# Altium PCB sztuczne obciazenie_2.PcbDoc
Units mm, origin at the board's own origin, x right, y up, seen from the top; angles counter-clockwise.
Board outline 83 x 78.5 mm, 2 copper layers (Top Layer, Bottom Layer); 51 components, 49 nets, 181 pads, 10 vias.
Unrouted connection lines stored in the file: 2.
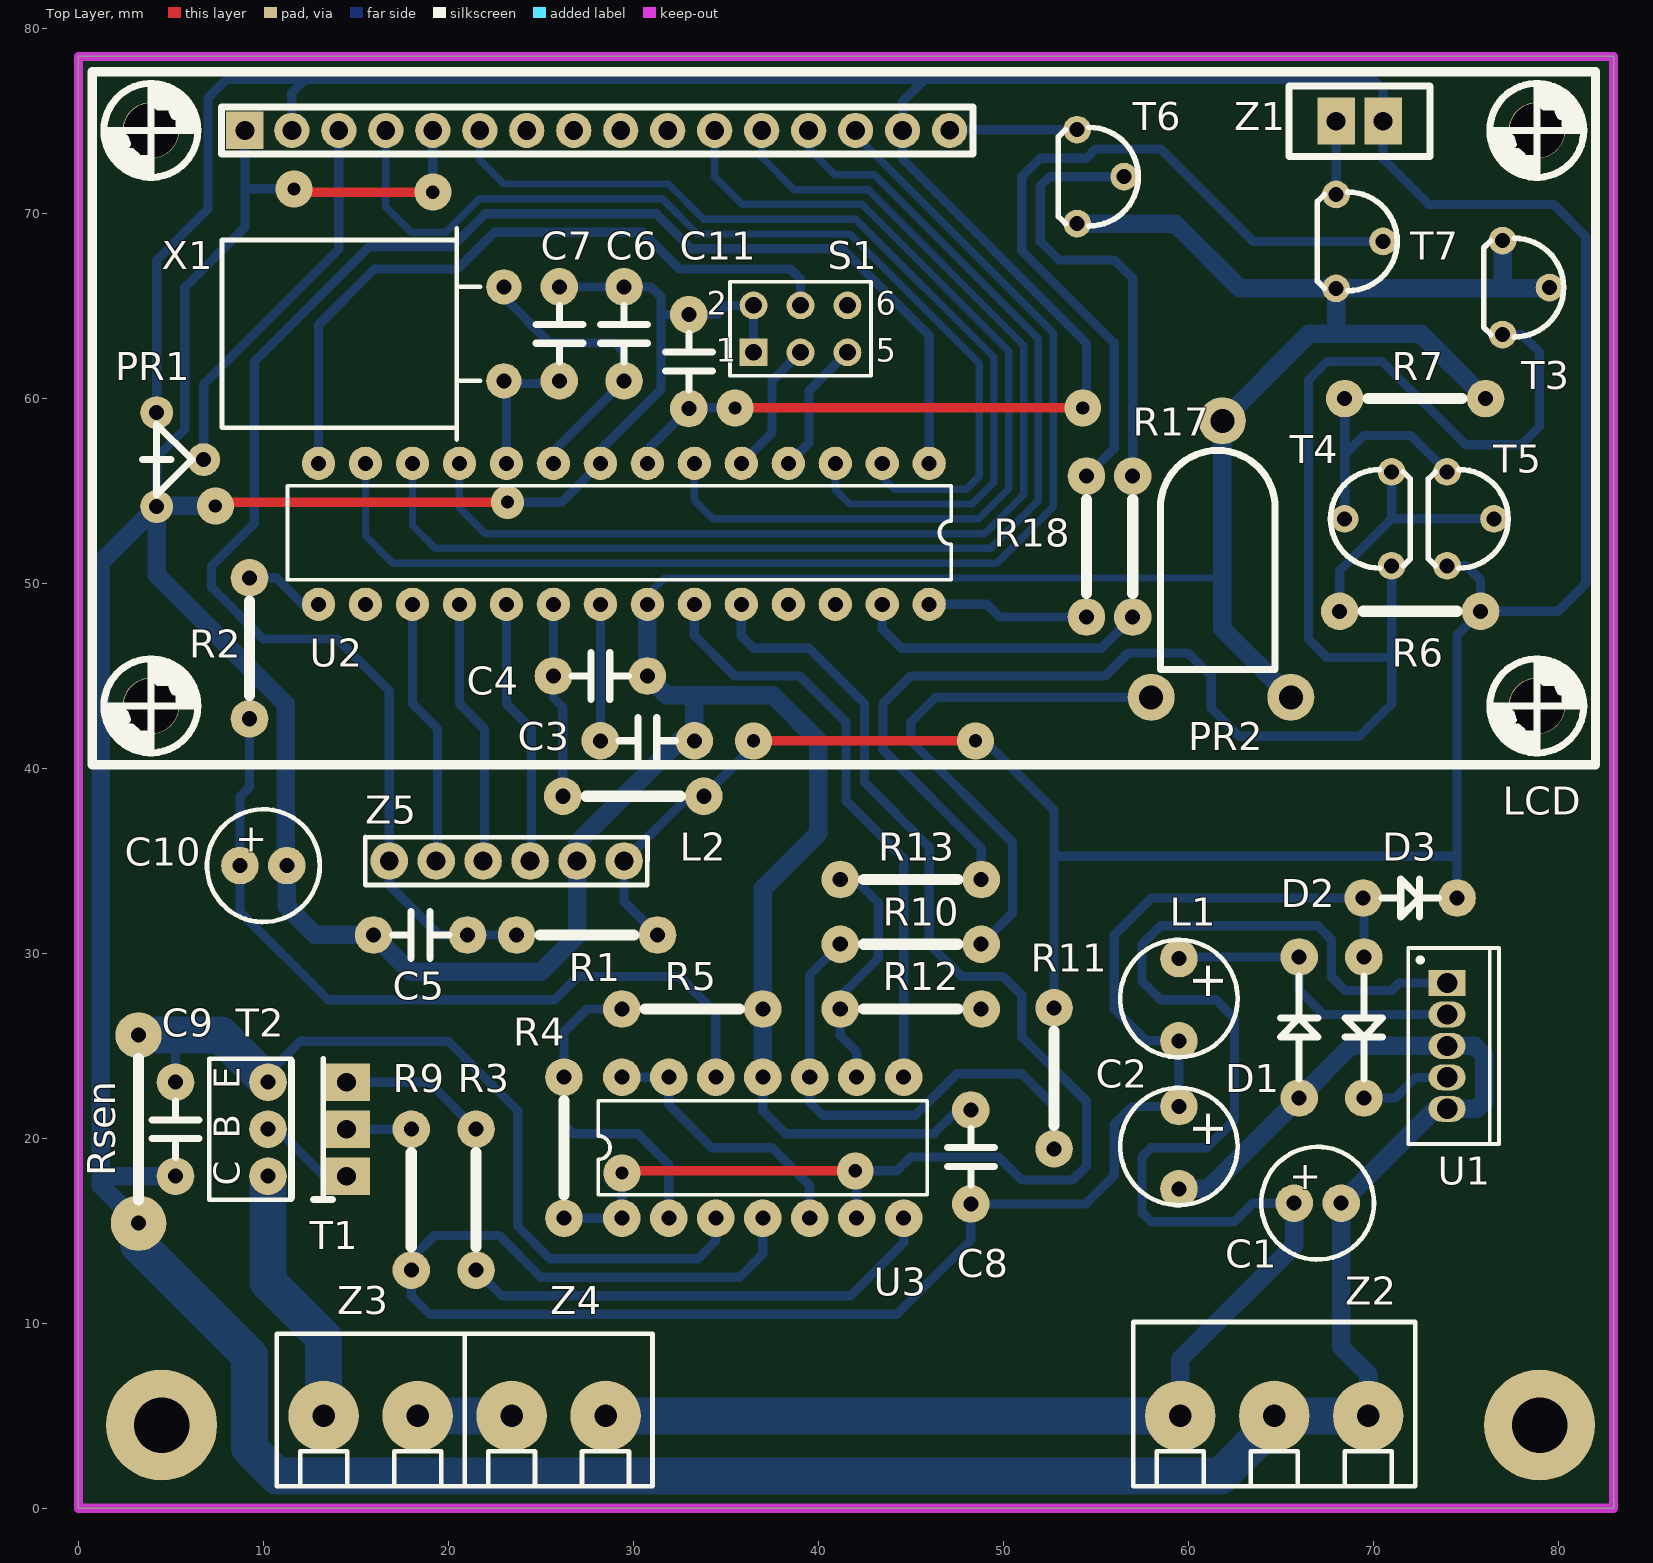
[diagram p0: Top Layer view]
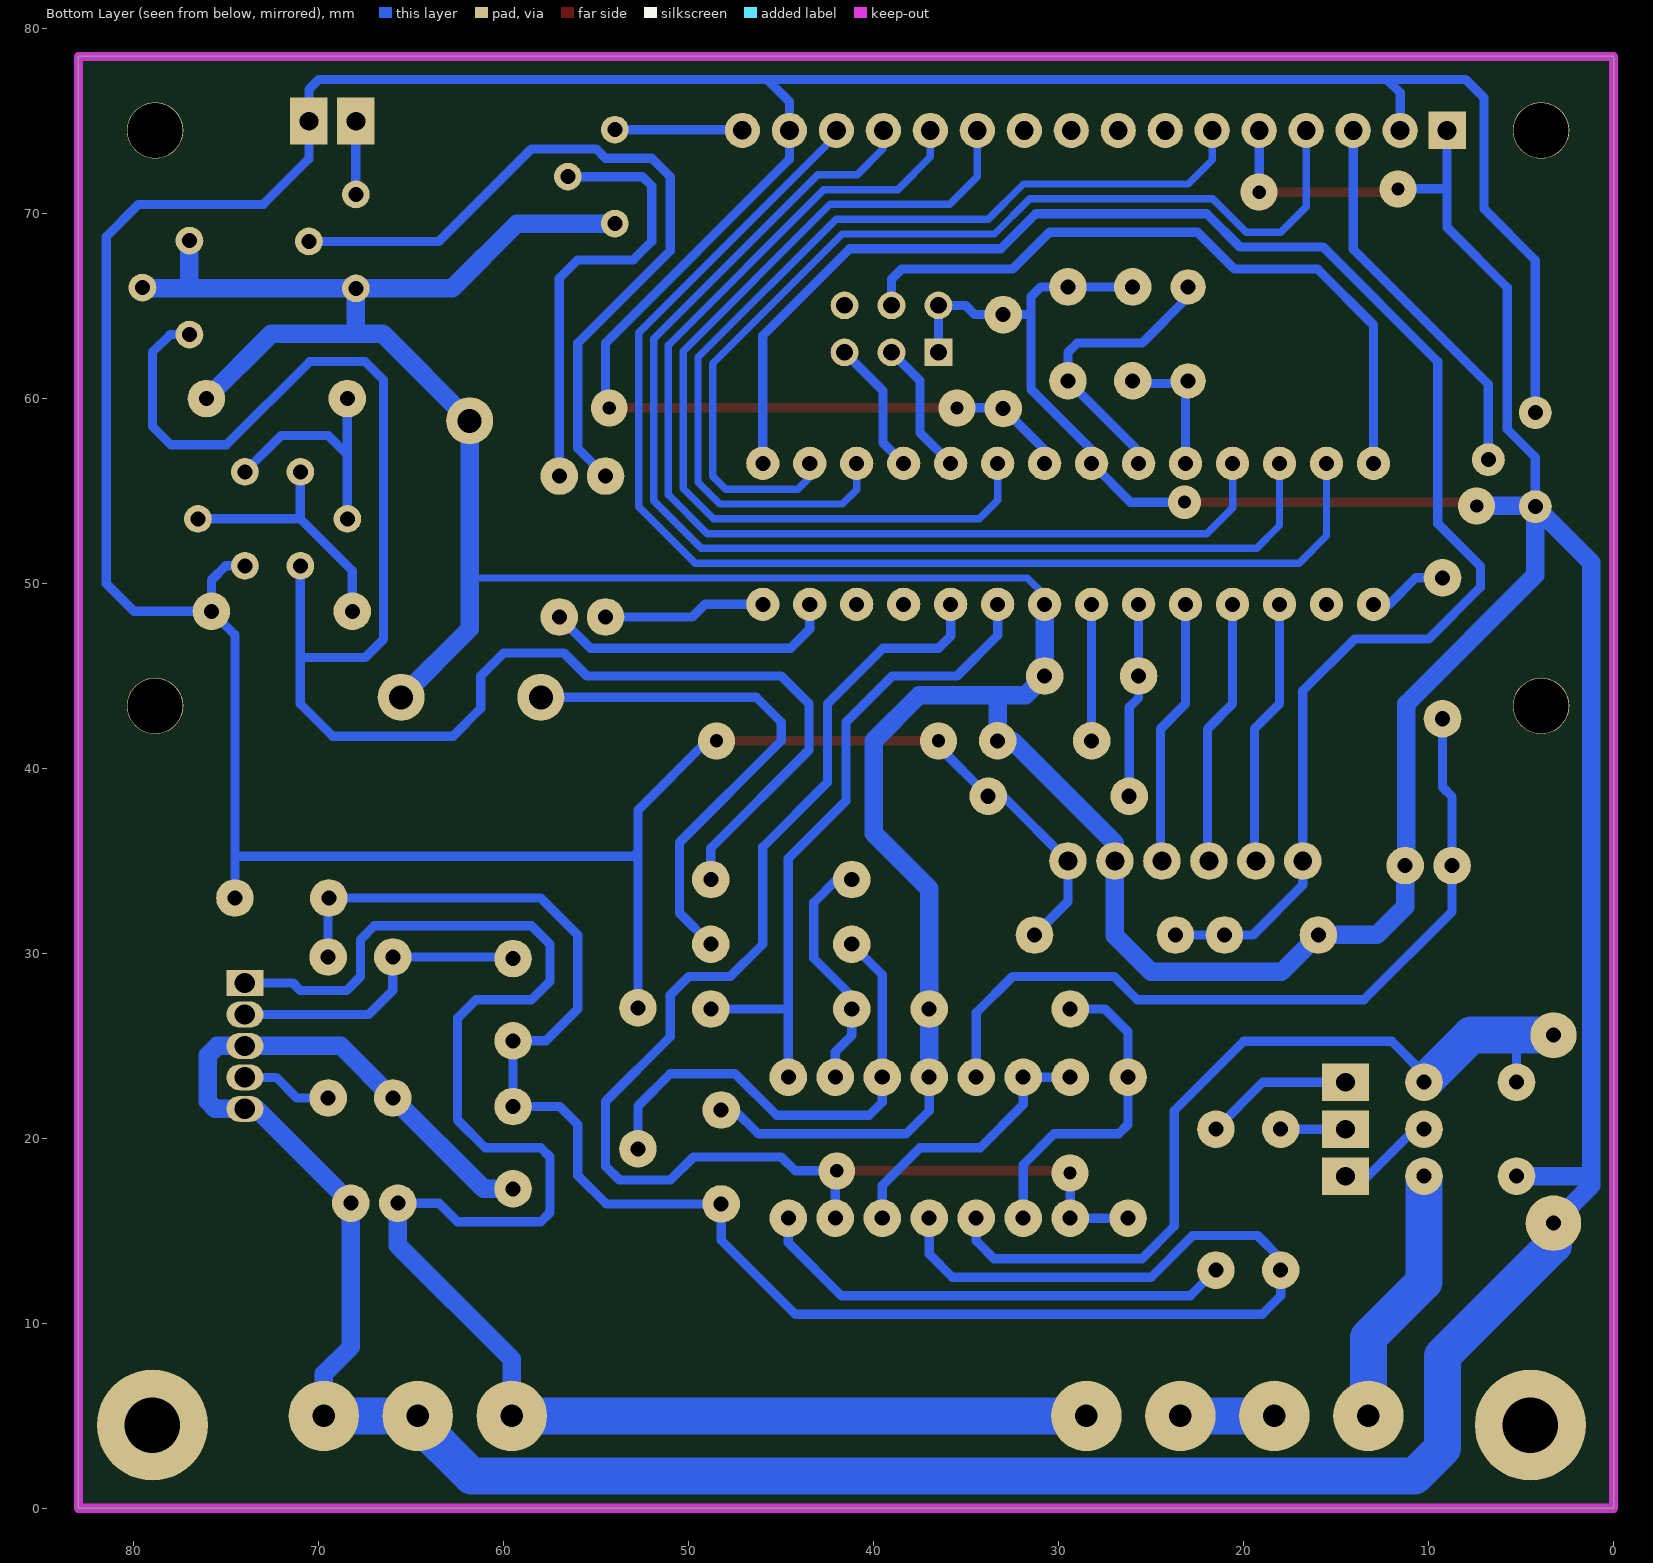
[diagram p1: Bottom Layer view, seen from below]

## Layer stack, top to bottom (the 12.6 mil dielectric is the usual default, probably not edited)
Top Layer: signal copper 0.0356
Dielectric: dielectric 0.32, FR-4, Dk 4.8
Bottom Layer: signal copper 0.0356

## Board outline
0,0 83,0 83,78.5 0,78.5

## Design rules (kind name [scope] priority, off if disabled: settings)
Clearance [All] p1: gap=0.3
PolygonConnect [All] p1: connectstyle=Relief reliefconductorwidth=0.254 reliefentries=4 polygonreliefangle="90 Angle"
RoutingVias [All] p1: holewidth=0.8 width=2 viastyle="Through Hole" minholewidth=0.711 minwidth=2 maxholewidth=1 maxwidth=2
SilkscreenOverComponentPads [All] p1: minsilkscreentomaskgap=0.254
SolderMaskExpansion [All] p1: expansion=0.102
Width [All] p1: maxlimit=3 minlimit=0.3 preferedwidth=0.5 minimp=50.000000 maximp=50.000000 favimp=50.000000
27 further rules are at their usual default settings.

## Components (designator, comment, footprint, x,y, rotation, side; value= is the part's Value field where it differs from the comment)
C1 "100uF" CE6 67,16.5 r0 top
C2 "100uF" CE7 59.5,19.5 r270 top
C3 "100n" C2 30.76,41.5 r0 top
C4 "100n" C2 28.22,45 r0 top
C5 "100n" C2 18.5,31 r180 top
C6 "C" C2 29.5,63.5 r270 top
C7 "C" C2 26,63.5 r90 top
C8 "100n" C2 48.25,19 r270 top
C9 "100n" C2 5.25,20.5 r90 top
C10 "2,2uF" CE6 10,34.75 r0 top
C11 "100n" C2 33,62 r270 top
D1 "" D3 66,26 r90 top
D2 "HER105" D3 69.5,26 r270 top
D3 "HER105" D2 72,33 r0 top
L1 "330uH" CE7 59.5,27.5 r270 top
L2 "" R3 30,38.5 r90 top
LCD "LCD 2x16" LCD16*2_B 9,74.5 r0 top locked
PR1 "" PR 5.5,56.7 r270 top
PR2 "POT" PR7 60,40 r90 top
R1 "10k" R3 27.5,31 r270 top
R2 "47k" R3 9.25,46.5 r180 top
R3 "100R" R3 21.5,16.69 r0 top
R4 "100k" R3 26.25,19.5 r0 top
R5 "47k+2,2k" R3 33.19,27 r90 top
R6 "R" R3 72,48.5 r90 top
R7 "R" R3 72.27,60 r270 top
R9 "10R" R3 18,16.69 r180 top
R10 "" R3 45,30.5 r90 top
R11 "" R3 52.75,23.25 r0 top
R12 "" R3 45,27 r90 top
R13 "" R3 45,34 r270 top
R17 "10k" R3 57,52 r0 top
R18 "10k" R3 54.5,52 r180 top
Rsen "0.11R/18W" R4 3.25,20.5 r0 top
S1 "Enkoder" HDR2X3 36.5,62.5 r0 top
T1 "BD139" BD1 14.5,20.5 r90 top
T2 "ISOBUV21" TUNIW 10.25,20.5 r90 top
T3 "BC557B" T_1 77,66 r270 top
T4 "BC557B" T_1 71,53.5 r90 top
T5 "BC557B" T_1 74,53.5 r270 top
T6 "NPN" T_1 54,72 r270 top
T7 "NPN" T_1 68,68.5 r270 top
U1 "LM2575T-5.0" T05A 74,25 r270 top
U2 "ATmega8-16PC" U28_MALA 46,56.5 r180 top
U3 "" U14 37,19.5 r0 top
X1 "" X 23,63.5 r180 top
Z1 "FAN" JMP2 69.27,75 r90 top
Z2 "Vin" ARK3 64.653,5 r180 top
Z3 "LOAD" ARK2 18.34,5 r180 top
Z4 "Vext" ARK2 28.5,5 r180 top
Z5 "ISP" "GOLDPIN 6" 31.5,25.5 r180 top

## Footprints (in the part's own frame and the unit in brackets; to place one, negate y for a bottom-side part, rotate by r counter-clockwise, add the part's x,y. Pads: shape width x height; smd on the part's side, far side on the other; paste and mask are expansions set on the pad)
ARK2 [mil]
  round 150 hole 48: 1(200,0) 2(0,0)
  silkscreen extent -100,-175 300,150
ARK3 [mil]
  round 150 hole 48: 1(200,0) 2(0,0) 3(-200,0)
  silkscreen extent -300,-200 300,150
BD1 [mil]
  rect 80x100 hole 40: 1(-100,0) 2(100,0) 3(0,0)
  silkscreen extent -150,30 150,70
C2 [mil]
  round 80 hole 32: 1(-100,0) 2(100,0)
  silkscreen extent -60,-50 60,50
CE6 [mil]
  round 80 hole 32: 1(-50,0) 2(50,0)
  silkscreen extent -120,-120 120,120
CE7 [mil]
  round 80 hole 32: 1(-87.5,0) 2(87.5,0)
  silkscreen extent -127,-125 122,125
D2 [mil]
  round 80 hole 32: 1(-100,0) 2(100,0)
  silkscreen extent -60,-40 60,40
D3 [mil]
  round 80 hole 32: 1(-150,0) 2(150,0)
  silkscreen extent -110,-40 110,40
"GOLDPIN 6" [mil]
  round 80 hole 40: 1(78.74,-374.02) 2(178.74,-374.02) 3(278.74,-374.02) 4(378.74,-374.02) 5(478.74,-374.02) 6(578.74,-374.02)
  silkscreen extent 29,-425 630,-323
HDR2X3 [mm] "Connector; Header; 3x2 Position"
  rect 1.5x1.5 hole 0.9: 1(0,0)
  round 1.5 hole 0.9: 2(0,2.54) 3(2.54,0) 4(2.54,2.54) 5(5.08,0) 6(5.08,2.54)
  silkscreen extent -1.27,-1.27 6.35,3.81
JMP2 [mil]
  rect 100x80 hole 40: 1(0,-50) 2(0,50)
  silkscreen extent -75,-150 75,150
LCD16*2_B [mil]
  round 120 hole 117: 0(-200,-1225) 0(-200,0) 0(2750,-1225) 0(2750,0)
  rect 80x80 hole 40: 1(0,0)
  round 75 hole 40: 2(100,0) 3(200,0) 4(300,0) 5(400,0) 6(500,0) 7(600,0) 8(700,0) 9(800,0) 10(900,0) 11(1000,0) 12(1100,0) 13(1200,0) 14(1300,0) 15(1400,0)
  round 75 hole 39.37: 16(1500,0)
  silkscreen extent -325,-1350 2875,125
PR [mil]
  round 70 hole 32: 1(100,-50) 2(0,50) 3(-100,-50)
  silkscreen extent -75,-80 75,25
PR7 [mm]
  round 2.54 hole 1.295: 1(3.85,2) 2(18.8,-1.85) 3(3.85,-5.55)
  silkscreen extent 5.35,-4.7 17.2,1.5
R3 [mil]
  round 80 hole 32: 1(0,-150) 2(0,150)
  silkscreen extent 0,-100 0,100
R4 [mm]
  round 3 hole 0.813: 1(0,-5.08)
  round 2.5 hole 0.813: 2(0,5.08)
  silkscreen extent 0,-3.81 0,3.81
T05A [mm] "TO, Thru-Hole, Vertical, Heatsink Mounted; 5 In-Line Leads; Pitch 1.70 mm"
  rect 1.4x2 hole 1.1: 1(-3.4,0)
  oval 1.4x2 hole 1.1: 2(-1.7,0) 3(0,0) 4(1.7,0) 5(3.4,0)
  silkscreen extent -5.3,-2.1 5.3,2.8, body extent -5.35,-2.15 5.35,2.85, height 19.6
T_1 [mm]
  round 1.5 hole 0.813: 1(2.54,0) 2(0,2.54) 3(-2.54,0)
  silkscreen extent -2.67,-1.02 2.67,3.3
TUNIW [mil]
  round 80 hole 32: 1(100,0) 2(0,0) 3(-100,0)
  silkscreen extent -150,-50 150,125
U14 [mil]
  round 80 hole 32: 1(-300,-150) 2(-200,-150) 3(-100,-150) 4(0,-150) 5(100,-150) 6(200,-150) 7(300,-150) 8(300,150) 9(200,150) 10(100,150) 11(0,150) 12(-100,150) 13(-200,150) 14(-300,150)
  silkscreen extent -350,-100 350,100
U28_MALA [mm]
  round 1.8 hole 0.813: 1(0,0) 2(2.54,0) 3(5.08,0) 4(7.62,0) 5(10.16,0) 6(12.7,0) 7(15.24,0) 8(17.78,0) 9(20.32,0) 10(22.86,0) 11(25.4,0) 12(27.94,0) 13(30.48,0) 14(33.02,0) 15(33.02,7.62) 16(30.48,7.62) 17(27.94,7.62) 18(25.4,7.62) 19(22.86,7.62) 20(20.32,7.62) 21(17.78,7.62) 22(15.24,7.62) 23(12.7,7.62) 24(10.16,7.62) 25(7.62,7.62) 26(5.08,7.62) 27(2.54,7.62) 28(0,7.62)
  silkscreen extent -1.19,1.21 34.7,6.3
X [mil]
  round 75 hole 32: 1(0,100) 2(0,-100)
  silkscreen extent 50,-225 600,225

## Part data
C1 C2 C10: library part EL, "Elektrolit"
C3 C4 C5 C8 C9 C11: library part C, "Kondensator"
C6 C7: "Kondensator"
D1: library part "D SCHOTTKY", "Dioda Schottky"
D2 D3: library part D, "Dioda"
L1 L2: library part L2, "Cewka"
LCD: library part LCD
PR1: library part POT, "Potencjometr"
PR2: "Potencjometr"
R1 R2 R3 R4 R5 R9 R10 R11 R12 R13 R17 R18 Rsen: library part R, "Rezystor"
R6 R7: "Rezystor"
T1 T2: library part NPN, "Tranzystor NPN"
T3 T4 T5: library part PNP, "Tranzystor PNP"
T6 T7: "Tranzystor NPN"
U1: "SIMPLE SWITCHER® 1A Step-Down Voltage Regulator, 5-pin TO-220"
U2: "8-Bit AVR Microcontroller with 8K Bytes of In-System Programmable Flash Memory"
U3: library part LM324
X1: library part X
Z1: library part JMP2
Z2: library part "ARK 3"
Z3 Z4: library part ARK2
Z5: library part GOLDPINX6

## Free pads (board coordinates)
  round 6 hole 3: 0(79,4.5) 1(4.5,4.5)

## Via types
v1: diameter 2, hole 0.711, Top Layer to Bottom Layer, 9 vias
v2: diameter 1.8, hole 0.711, Top Layer to Bottom Layer, 1 vias

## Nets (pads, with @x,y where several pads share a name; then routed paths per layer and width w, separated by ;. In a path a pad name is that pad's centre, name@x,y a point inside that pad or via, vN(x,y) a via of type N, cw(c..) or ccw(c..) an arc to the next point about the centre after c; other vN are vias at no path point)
+6V: C2.1 C8.2 D2.1 D3.1 L1.2 R9.2 U3.4 | length 103.5
  Bottom Layer w0.5: U3.4 37,13.75 35.75,12.5 25,12.5 22.75,14.75 19.25,14.75 18,13.5 R9.2 18,11.5 19,10.5 44.25,10.5 48.25,14.5 C8.2 54.46,16.46 56,18 56,20.75 56.972,21.722 C2.1 L1.2 57.722,25.278 56,27 56,31 58,33 D3.1 69.5,32.96 D2.1
GND: C1.2 C2.2 C3.2 C4.2 C5.2 C6.1 C7.2 C8.1 C9.1 C10.2 C11.1 D1.1 LCD.1 LCD.5 PR1.1 PR2.2 PR2.3 R5.1 R7.2 Rsen.1 S1.1 S1.2 T3.2 T3.3 T6.1 T7.1 U1.3 U1.5 U2.8 U2.22 U3.11 Z2.2 Z2.3 Z5.2 | length 457.5
  Top Layer w0.5: v1(7.4,54.2) 7.4,54.4 v2(23.2,54.4) ; v1(11.66,71.34) 11.66,71.16 v1(19.16,71.16)
  Bottom Layer w0.4: U2.22@30.76,49.36 31.7,50.3 61.85,50.3
  Bottom Layer w0.5: PR1.1@4.27,54.2 PR1.1 4.23,56.83 5.75,58.35 5.75,66 9,69.25 9,71.5 ; LCD.1 9,71.5 ; v1(11.66,71.34) 9.16,71.34 9,71.5 ; v1(19.16,71.16) LCD.5 ; v2(23.2,54.4) 26.12,54.4 U2.8 28.22,57.22 31.5,60.5 31.5,64.5 ; C7.2@25.46,66.04 C7.2 C6.1 30.96,66.04 31.5,65.5 31.5,64.5 ; U2.22 U2.22@30.76,49.36 ; S1.1 S1.2 35.04,65.04 34.54,64.54 C11.1 31.54,64.54 31.5,64.5 ; 36.81,33.31 37,33.5 ; U3.11 37,21.5 38.25,20.25 46.25,20.25 47.54,21.54 C8.1
  Bottom Layer w1: Rsen.1 1.2,17.47 1.2,18 ; PR1.1@4.27,54.2 v1(7.4,54.2) ; C9.1 1.24,17.96 1.2,18 ; U2.22 C4.2 31.81,43.95 33,43.95 ; U3.11 R5.1 37,33.5 40,36.5 40,41.5 37.55,43.95 33,43.95 ; T6.1 59.29,69.46 62.79,65.96 T7.1 ; C2.2 61.087,17.277 D1.1 68.81,25 U1.3 75.5,25 76,24.5 76,22 75.6,21.6 U1.5 73.37,21.6 C1.2 68.27,8.73 69.733,7.267 Z2.3 ; PR2.3 61.85,47.55 61.85,50.3 PR2.2 66.55,63.5 68,63.5 ; T7.1@68.04,66 T7.1 ; R7.2 72.58,63.5 68,63.5 ; T3.3 77,65.96 ; T3.2 79.5,65.96 77,65.96 ; 1.2,18 1.2,51.13 PR1.1 4.245,54.145 4.245,50.445 11.2,43.49 11.2,34.82 C10.2 11.27,32.53 12.8,31 C5.2 17.96,29 25,29 26.96,30.96 Z5.2 26.96,35.96 32.5,41.5 C3.2 33.3,43.65 33,43.95 ; 68,63.5 T7.1 ; T7.1 77,65.96
  Bottom Layer w2: Rsen.1 3.25,14.25 9.25,8.25 9.25,3.25 10.75,1.75 61.75,1.75 64.653,4.653 Z2.2 Z2.3
NetC3_1: C3.1 U2.21 | length 7.4
  Bottom Layer w0.5: C3.1 U2.21
NetC4_1: C4.1 L2.2 U2.20 | length 10.6
  Bottom Layer w0.5: U2.20 C4.1 25.68,43.82 26.19,43.31 L2.2
NetC5_1: C5.1 R1.1 U2.1 Z5.6 | length 93
  Bottom Layer w0.5: R1.1 C5.1 19.5,31 16.8,33.7 Z5.6 16.8,44.2 14,47 10,47 7.2,49.8 7.2,50.95 9.5,53.25 9.5,62 15.7,68.2 20.2,68.2 22,70 31.237,70 33.137,68.1 41.3,68.1 46,63.4 U2.1
NetC6_2: C6.2 U2.9 X1.2 | length 15.9
  Bottom Layer w0.5: X1.2 23,65.5 25.5,63 29,63 29.5,62.5 C6.2 25.68,57.14 U2.9
NetC7_1: C7.1 U2.10 X1.1 | length 7
  Bottom Layer w0.5: U2.10 23.14,60.82 C7.1@25.86,60.82
NetC9_2: C9.2 Rsen.2 T2.1 U3.3 | length 46.1
  Bottom Layer w0.5: C9.2 5.25,25.58 ; T2.1 10.25,23.5 12,25.25 20,25.25 23.75,21.5 23.75,15.25 25.5,13.5 33.5,13.5 34.46,14.46 U3.3
  Bottom Layer w2: Rsen.2 5.25,25.58 7.71,25.58 T2.1
NetC10_1: C10.1 R2.2 U3.12 | length 43.2
  Bottom Layer w0.5: R2.2 9.25,39 8.73,38.48 C10.1 8.73,32.27 13.5,27.5 25.75,27.5 27,28.75 32.5,28.75 34.46,26.79 U3.12
NetD1_2: D1.2 L1.1 U1.2 | length 16.9
  Bottom Layer w0.5: L1.1 59.587,29.81 D1.2 66,28 67.3,26.7 U1.2
NetD2_2: D2.2 U1.4 | length 5
  Bottom Layer w0.5: D2.2 71.19,22.19 72.3,23.3 U1.4
NetLCD_3: LCD.3 PR1.2 | length 20.4
  Bottom Layer w0.5: PR1.2@6.77,57.1 6.77,60.77 14.08,68.08 LCD.3
NetLCD_4: LCD.4 U2.2 | length 53.9
  Bottom Layer w0.4: LCD.4 16.62,70.38 18,69 19.869,69 21.669,70.8 31.569,70.8 33.469,68.9 41.7,68.9 48.7,61.9 48.7,55.8 48,55.1 44.1,55.1 43.46,55.74 U2.2
NetLCD_6: LCD.6 U2.3 | length 51.4
  Bottom Layer w0.4: LCD.6 21.7,72.9 23,71.6 31.9,71.6 33.8,69.7 42.031,69.7 49.5,62.231 49.5,55.469 48.331,54.3 41.7,54.3 40.92,55.08 U2.3
NetLCD_11: LCD.11 U2.6 | length 49.8
  Bottom Layer w0.4: U2.6 33.3,54.5 34.3,53.5 48.663,53.5 50.3,55.137 50.3,62.563 42.363,70.5 35.9,70.5 34.4,72 LCD.11
NetLCD_12: LCD.12 U2.11 | length 62.3
  Bottom Layer w0.4: U2.11 20.6,54.1 22,52.7 48.994,52.7 51.1,54.806 51.1,62.894 42.694,71.3 38.7,71.3 36.94,73.06 LCD.12
NetLCD_13: LCD.13 U2.12 | length 65.2
  Bottom Layer w0.4: U2.12 18.06,53.14 19.3,51.9 49.325,51.9 51.9,54.475 51.9,63.225 43.025,72.1 40.9,72.1 39.48,73.52 LCD.13
NetLCD_14: LCD.14 U2.13 | length 67.8
  Bottom Layer w0.4: U2.13 15.52,52.58 17,51.1 49.657,51.1 52.7,54.143 52.7,63.557 42.02,74.237 LCD.14
NetLCD_16: LCD.16 T6.3 | length 6.9
  Bottom Layer w0.5: LCD.16 47.14,74.54 T6.3
NetPR2_1: PR2.1 R10.1 | length 28.5
  Bottom Layer w0.5: R10.1 50.5,32.19 50.5,36 45,41.5 45,42.5 46.35,43.85 PR2.1
NetR2_1: R2.1 U2.15 | length 4.3
  Bottom Layer w0.5: R2.1 10.69,50.31 12.12,48.88 U2.15
NetR3_1: R3.1 U3.7 | length 26.2
  Bottom Layer w0.5: R3.1 22.88,11.5 41.75,11.5 44.62,14.37 U3.7
NetR3_2: R3.2 T1.2 | length 8.1
  Bottom Layer w0.5: T1.2 18.96,23.04 R3.2
NetR4_1: R4.1 U2.24 U3.1 U3.6 | length 75.7
  Top Layer w0.5: v1(29.38,18.13) 29.5,18.25 v1(42,18.25)
  Bottom Layer w0.5: R4.1 U3.1 v1(29.38,18.13) ; U2.24 35.84,47.16 36.5,46.5 39.5,46.5 42.5,43.5 42.5,39.25 46,35.75 46,30.5 47.75,28.75 50,28.75 51,27.75 51,25.5 54.5,22 54.5,18.5 53.75,17.75 51,17.75 49.75,19 45,19 44.25,18.25 v1(42,18.25) 42.08,18.17 U3.6
NetR4_2: R4.2 R5.2 U3.2 | length 18.1
  Bottom Layer w0.5: R5.2 27.5,27 26.25,25.75 R4.2 26.25,20.75 26.75,20.25 30.25,20.25 31.92,18.58 U3.2
NetR6_2: R6.2 T4.1 T5.2 | length 14.2
  Bottom Layer w0.5: R6.2 68.19,50.69 71,53.5 ; T4.1 71,53.5 ; T5.2 71,53.5
NetR7_1: R7.1 T4.2 T5.3 | length 13.7
  Bottom Layer w0.5: T4.2 68.46,56.96 ; R7.1 68.46,56.96 ; T5.3@74,56.5 T5.3 72.04,58 69.5,58 68.46,56.96
NetR9_1: R9.1 T1.3 | length 3.5
  Bottom Layer w0.5: T1.3 R9.1
NetR10_2: R10.2 R11.1 U3.10 | length 26.7
  Bottom Layer w0.5: R10.2 39.54,28.85 U3.10 39.54,21.96 40.25,21.25 45.25,21.25 47.5,23.5 51,23.5 52.75,21.75 R11.1
NetR12_1: R12.1 U2.23 U3.8 | length 36.5
  Bottom Layer w0.5: U2.23 33.3,47.2 35.5,45 39,45 41.5,42.5 41.5,38.25 44.62,35.13 44.62,27 ; U3.8 44.62,27 ; R12.1 44.62,27
NetR12_2: R12.2 R13.1 U3.9 | length 13.2
  Bottom Layer w0.5: R13.1 42,34 43.25,32.75 43.25,29.75 41.19,27.69 R12.2 41.19,25.56 42.08,24.67 U3.9
NetR13_2: R13.2 T3.1 T4.3 | length 91.9
  Bottom Layer w0.5: R13.2 48.81,35.69 43.5,41 43.5,43.5 45,45 55.5,45 56.75,46.25 60,46.25 61.25,45 61.25,43.25 62.75,41.75 69.25,41.75 71,43.5 71,46 ; T4.3 71,46 ; T3.1 78.04,63.46 79,62.5 79,58.5 78,57.5 75,57.5 70.5,62 67.5,62 66.5,61 66.5,47 67.5,46 71,46
NetR17_1: R17.1 U2.27 | length 16
  Bottom Layer w0.5: U2.27 43.46,47.54 44.5,46.5 55.31,46.5 R17.1
NetR17_2: R17.2 T6.2 | length 24.3
  Bottom Layer w0.5: T6.2 52.5,72 52,71.5 52,68.5 53,67.5 56,67.5 57,66.5 R17.2
NetR18_1: R18.1 T7.2 | length 41.5
  Bottom Layer w0.5: R18.1 56,57.31 56,63 51,68 51,72 52,73 54.5,73 55,73.5 58.5,73.5 63.5,68.5 T7.2 T7.2@70.29,68.75
NetR18_2: R18.2 U2.28 | length 8.8
  Bottom Layer w0.5: U2.28 49.12,48.88 49.81,48.19 R18.2
NetS1_3: S1.3 U2.5 | length 7.3
  Bottom Layer w0.5: U2.5 37.5,58.16 37.5,60.96 S1.3
NetS1_4: S1.4 U2.14 | length 38.1
  Bottom Layer w0.5: U2.14 12.98,63.98 16,67 20.5,67 22.5,69 30.5,69 32.5,67 38.5,67 39.04,66.46 S1.4
NetS1_5: S1.5 U2.4 | length 7.3
  Bottom Layer w0.5: U2.4 39.5,57.62 39.5,60.42 S1.5
NetT1_1: T1.1 T2.2 | length 5.3
  Bottom Layer w0.5: T2.2 10.75,20.5 13.29,17.96 T1.1
NetT2_3: T2.3 Z3.1 | length 14.2
  Bottom Layer w2: T2.3 10.25,12.25 13.26,9.24 Z3.1
NetT7_3: T7.3 Z1.2 | length 4
  Bottom Layer w0.5: T7.3 Z1.2
NetU2_17: U2.17 Z5.5 | length 13.4
  Bottom Layer w0.5: U2.17 18.06,43.5 19.42,42.14 Z5.5@19.42,36
NetU2_18: U2.18 Z5.4 | length 13.4
  Bottom Layer w0.5: U2.18 20.6,43.5 21.96,42.14 Z5.4@21.96,36
NetU2_19: U2.19 Z5.3 | length 13.4
  Bottom Layer w0.5: U2.19 23.14,43.5 24.5,42.14 Z5.3@24.5,36
NetU3_5: U3.5 U3.13 U3.14 | length 15.2
  Bottom Layer w0.5: U3.14 U3.13 31.92,21.83 34.25,19.5 37.5,19.5 39.54,17.46 U3.5
NetZ3_2: Z3.2 Z4.1 | length 5.1
  Bottom Layer w2: Z3.2 Z4.1
VCC: C11.2 D3.2 L2.1 LCD.2 LCD.15 PR1.3 R1.2 R6.1 R11.2 T5.1 U2.7 Z1.1 Z5.1 | length 259.6
  Top Layer w0.5: v1(35.5,59.5) v1(54.3,59.5) v1@54.5,59.5 ; v1(36.5,41.5) v1(48.5,41.5) v1@49,41.5
  Bottom Layer w0.5: PR1.3@4.23,59.7 4.23,67.48 7,70.25 7,76.25 8,77.25 12.25,77.25 ; LCD.2 11.54,76.54 12.25,77.25 ; U2.7 30.76,57.22 C11.2 33.04,59.5 v1(35.5,59.5) ; R1.2 29.5,32.81 Z5.1 33,38.5 L2.1 36.5,41.19 v1(36.5,41.5) ; v1(48.5,41.5) 49,41.5 52.75,37.75 52.75,35.5 ; R11.2 52.75,35.5 ; v1@54.5,59.5 54.5,63 44.56,72.94 LCD.15 44.56,76.06 45.75,77.25 ; T5.1 75.04,50.96 75.81,50.19 R6.1 ; D3.2 74.54,35.25 ; 12.25,77.25 45.75,77.25 ; 45.75,77.25 70,77.25 70.54,76.71 Z1.1 70.54,72.96 73,70.5 79.75,70.5 81.5,68.75 81.5,50 80,48.5 R6.1 ; 52.75,35.5 53,35.25 74.54,35.25 ; 74.54,35.25 74.54,47.23 R6.1
VIN: C1.1 U1.1 Z2.1 Z4.2 | length 95.8
  Bottom Layer w0.5: C1.1 63.5,16.5 62.5,15.5 58,15.5 57.5,16 57.5,19 58,19.5 61,19.5 62.5,21 62.5,26.5 61.5,27.5 58.5,27.5 57.5,28.5 57.5,30.5 58.5,31.5 67,31.5 67.75,30.75 67.75,28.75 68.5,28 71,28 71.4,28.4 U1.1
  Bottom Layer w1: Z2.1 59.573,8.073 65.73,14.23 C1.1
  Bottom Layer w2: Z4.2 Z2.1
pads on no net: LCD.0 LCD.7 LCD.8 LCD.9 LCD.10 S1.6 U2.16 U2.25 U2.26

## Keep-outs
Keep-Out Layer:
  the board outline again, w0.5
